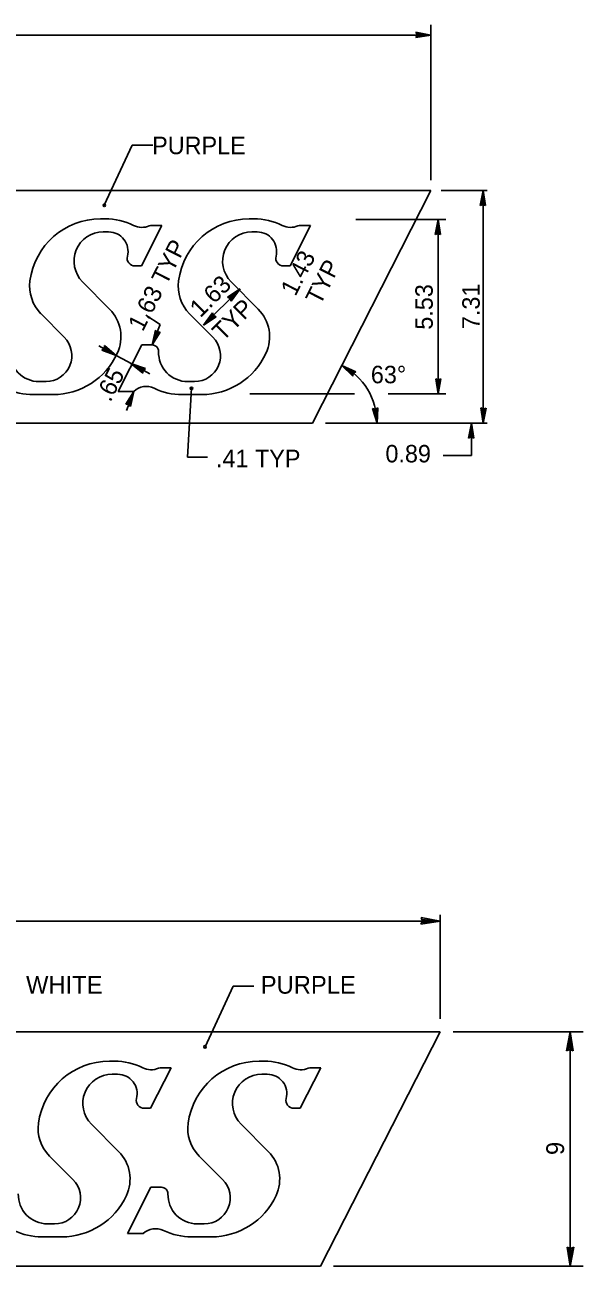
# Model space of a CAD drawing. Extents: x 10268197 to 10269179, y 2141503 to 2142677.
# Drawn here: x 10268622.88 to 10268641.86, y 2142123.35 to 2142165.55 of the extents above; entities that cross this region are included whole.
import ezdxf

# ---------------------------------------------------------------- set-up
doc = ezdxf.new("R2010")
doc.units = 0
for name, color, linetype in [('1', 7, 'Continuous'), ('21', 7, 'Continuous'), ('Default', 7, 'Continuous')]:
    doc.layers.add(name, color=color, linetype=linetype)

msp = doc.modelspace()

# ---------------------------------------------------------------- linework, layer by layer
at = {"layer": '1'}
for p, q in [((10268636.689, 2142160.267), (10268636.689, 2142165.546)), ((10268617.622, 2142165.194), (10268636.689, 2142165.194)), ((10268636.216, 2142165.203), (10268636.175, 2142165.112)), ((10268636.689, 2142165.194), (10268636.175, 2142165.112)), ((10268636.689, 2142165.194), (10268636.178, 2142165.293)), ((10268636.178, 2142165.293), (10268636.216, 2142165.203)), ((10268636.689, 2142165.194), (10268636.197, 2142165.16)), ((10268636.689, 2142165.194), (10268636.198, 2142165.246)), ((10268626.531, 2142161.456), (10268625.584, 2142159.412)), ((10268627.229, 2142161.456), (10268626.531, 2142161.456)), ((10268637.04, 2142159.916), (10268638.595, 2142159.916)), ((10268638.462, 2142159.916), (10268638.363, 2142159.405)), ((10268638.462, 2142159.916), (10268638.411, 2142159.424)), ((10268638.462, 2142152.007), (10268638.462, 2142159.916)), ((10268638.462, 2142159.916), (10268638.543, 2142159.402)), ((10268638.462, 2142159.916), (10268638.496, 2142159.424)), ((10268638.363, 2142159.405), (10268638.454, 2142159.442)), ((10268638.454, 2142159.442), (10268638.543, 2142159.402)), ((10268634.139, 2142158.927), (10268637.197, 2142158.927)), ((10268636.931, 2142158.927), (10268636.832, 2142158.416)), ((10268636.931, 2142158.927), (10268636.879, 2142158.436)), ((10268636.931, 2142152.996), (10268636.931, 2142158.927)), ((10268636.931, 2142158.927), (10268637.012, 2142158.413)), ((10268636.931, 2142158.927), (10268636.965, 2142158.435)), ((10268636.832, 2142158.416), (10268636.922, 2142158.454)), ((10268636.922, 2142158.454), (10268637.012, 2142158.413)), ((10268628.955, 2142155.33), (10268630.198, 2142156.573)), ((10268630.198, 2142156.573), (10268629.767, 2142156.282)), ((10268629.767, 2142156.282), (10268629.858, 2142156.244)), ((10268630.198, 2142156.573), (10268629.814, 2142156.262)), ((10268629.858, 2142156.244), (10268629.892, 2142156.152)), ((10268630.198, 2142156.573), (10268629.874, 2142156.201)), ((10268630.198, 2142156.573), (10268629.892, 2142156.152)), ((10268627.483, 2142155.362), (10268626.994, 2142155.673)), ((10268628.955, 2142155.33), (10268629.261, 2142155.751)), ((10268628.955, 2142155.33), (10268629.279, 2142155.702)), ((10268628.955, 2142155.33), (10268629.339, 2142155.641)), ((10268628.955, 2142155.33), (10268629.387, 2142155.622)), ((10268629.295, 2142155.659), (10268629.261, 2142155.751)), ((10268629.387, 2142155.622), (10268629.295, 2142155.659)), ((10268627.209, 2142154.662), (10268627.483, 2142155.362)), ((10268627.209, 2142154.662), (10268627.32, 2142155.171)), ((10268627.209, 2142154.662), (10268627.356, 2142155.133)), ((10268627.209, 2142154.662), (10268627.487, 2142155.102)), ((10268627.209, 2142154.662), (10268627.435, 2142155.101)), ((10268627.388, 2142155.1), (10268627.32, 2142155.171)), ((10268627.487, 2142155.102), (10268627.388, 2142155.1)), ((10268625.992, 2142154.306), (10268625.398, 2142154.63)), ((10268626.378, 2142154.096), (10268625.992, 2142154.306)), ((10268627.13, 2142153.686), (10268626.378, 2142154.096)), ((10268633.656, 2142153.965), (10268634.132, 2142153.753)), ((10268633.656, 2142153.965), (10268634.031, 2142153.603)), ((10268633.656, 2142153.965), (10268634.04, 2142153.654)), ((10268633.656, 2142153.965), (10268634.088, 2142153.726)), ((10268634.049, 2142153.7), (10268634.132, 2142153.753)), ((10268634.031, 2142153.603), (10268634.049, 2142153.7)), ((10268636.931, 2142152.996), (10268636.849, 2142153.51)), ((10268636.938, 2142153.469), (10268636.849, 2142153.51)), ((10268636.931, 2142152.996), (10268636.896, 2142153.488)), ((10268636.931, 2142152.996), (10268637.029, 2142153.507)), ((10268636.931, 2142152.996), (10268636.982, 2142153.487)), ((10268637.029, 2142153.507), (10268636.938, 2142153.469)), ((10268626.592, 2142153.085), (10268626.313, 2142152.645)), ((10268626.592, 2142153.085), (10268626.335, 2142152.43)), ((10268626.592, 2142153.085), (10268626.364, 2142152.646)), ((10268626.592, 2142153.085), (10268626.444, 2142152.614)), ((10268626.592, 2142153.085), (10268626.48, 2142152.576)), ((10268628.414, 2142150.852), (10268628.549, 2142153.189)), ((10268630.526, 2142152.996), (10268634.088, 2142152.996)), ((10268635.236, 2142152.996), (10268637.197, 2142152.996)), ((10268626.313, 2142152.645), (10268626.411, 2142152.647)), ((10268626.411, 2142152.647), (10268626.48, 2142152.576)), ((10268634.856, 2142152.007), (10268634.704, 2142152.505)), ((10268634.798, 2142152.477), (10268634.704, 2142152.505)), ((10268634.856, 2142152.007), (10268634.753, 2142152.49)), ((10268634.884, 2142152.527), (10268634.798, 2142152.477)), ((10268634.856, 2142152.007), (10268634.839, 2142152.501)), ((10268634.856, 2142152.007), (10268634.884, 2142152.527)), ((10268638.462, 2142152.007), (10268638.38, 2142152.521)), ((10268638.47, 2142152.48), (10268638.38, 2142152.521)), ((10268638.462, 2142152.007), (10268638.427, 2142152.499)), ((10268638.462, 2142152.007), (10268638.561, 2142152.518)), ((10268638.462, 2142152.007), (10268638.513, 2142152.499)), ((10268638.561, 2142152.518), (10268638.47, 2142152.48)), ((10268633.098, 2142152.007), (10268638.595, 2142152.007)), ((10268638.061, 2142152.007), (10268637.962, 2142151.497)), ((10268638.061, 2142152.007), (10268638.01, 2142151.516)), ((10268638.061, 2142150.909), (10268638.061, 2142152.007)), ((10268638.061, 2142152.007), (10268638.143, 2142151.494)), ((10268638.061, 2142152.007), (10268638.096, 2142151.515)), ((10268637.962, 2142151.497), (10268638.053, 2142151.534)), ((10268638.053, 2142151.534), (10268638.143, 2142151.494)), ((10268628.414, 2142150.852), (10268629.097, 2142150.852)), ((10268638.061, 2142150.909), (10268637.106, 2142150.909)), ((10268636.996, 2142131.752), (10268636.996, 2142135.291)), ((10268617.796, 2142135.07), (10268636.996, 2142135.07)), ((10268629.961, 2142132.861), (10268629.008, 2142130.802)), ((10268630.664, 2142132.861), (10268629.961, 2142132.861)), ((10268637.439, 2142131.31), (10268641.863, 2142131.31)), ((10268641.421, 2142123.346), (10268641.421, 2142131.31)), ((10268633.381, 2142123.346), (10268641.863, 2142123.346))]:
    msp.add_line(p, q, dxfattribs=at)
for centre, radius in [((10268625.584, 2142159.412), 0.0439), ((10268628.549, 2142153.189), 0.0439), ((10268629.008, 2142130.802), 0.0442)]:
    msp.add_circle(centre, radius, dxfattribs=at)
msp.add_arc((10268632.659, 2142152.008), 2.197, 0, 63.0012, dxfattribs=at)
at = {"layer": '21'}
for p, q in [((10268625.59, 2142154.639), (10268625.58, 2142154.54)), ((10268625.992, 2142154.306), (10268625.585, 2142154.587)), ((10268625.992, 2142154.306), (10268625.59, 2142154.639)), ((10268625.58, 2142154.54), (10268625.501, 2142154.481)), ((10268625.992, 2142154.306), (10268625.501, 2142154.481)), ((10268625.992, 2142154.306), (10268625.543, 2142154.512)), ((10268626.49, 2142154.032), (10268626.981, 2142153.858)), ((10268626.49, 2142154.032), (10268626.892, 2142153.7)), ((10268626.49, 2142154.032), (10268626.897, 2142153.752)), ((10268626.49, 2142154.032), (10268626.939, 2142153.826)), ((10268626.892, 2142153.7), (10268626.902, 2142153.798)), ((10268626.902, 2142153.798), (10268626.981, 2142153.858))]:
    msp.add_line(p, q, dxfattribs=at)
at = {"layer": 'Default'}
for p, q in [((10268611.626, 2142159.916), (10268636.689, 2142159.916)), ((10268632.66, 2142152.007), (10268636.689, 2142159.916)), ((10268625.453, 2142158.949), (10268625.619, 2142158.949)), ((10268630.505, 2142158.949), (10268630.672, 2142158.949)), ((10268625.731, 2142158.507), (10268625.542, 2142158.507)), ((10268627.543, 2142158.728), (10268626.845, 2142157.347)), ((10268627.213, 2142158.728), (10268627.543, 2142158.728)), ((10268630.783, 2142158.507), (10268630.594, 2142158.507)), ((10268632.595, 2142158.728), (10268631.897, 2142157.347)), ((10268632.266, 2142158.728), (10268632.595, 2142158.728)), ((10268626.845, 2142157.347), (10268626.625, 2142157.347)), ((10268631.897, 2142157.347), (10268631.677, 2142157.347)), ((10268624.843, 2142156.806), (10268625.764, 2142155.879)), ((10268629.896, 2142156.806), (10268630.817, 2142155.879)), ((10268624.223, 2142154.928), (10268623.432, 2142155.724)), ((10268629.275, 2142154.928), (10268628.484, 2142155.724)), ((10268626.058, 2142153.085), (10268626.856, 2142154.662)), ((10268626.856, 2142154.662), (10268627.209, 2142154.662)), ((10268623.364, 2142153.417), (10268623.602, 2142153.417)), ((10268628.417, 2142153.417), (10268628.654, 2142153.417)), ((10268623.837, 2142152.974), (10268623.177, 2142152.974)), ((10268626.592, 2142153.085), (10268626.058, 2142153.085)), ((10268628.89, 2142152.974), (10268628.229, 2142152.974)), ((10268610.892, 2142152.007), (10268632.66, 2142152.007)), ((10268636.996, 2142135.07), (10268636.353, 2142135.195)), ((10268636.353, 2142135.195), (10268636.401, 2142135.08)), ((10268636.401, 2142135.08), (10268636.349, 2142134.967)), ((10268636.996, 2142135.07), (10268636.349, 2142134.967)), ((10268636.996, 2142135.07), (10268636.377, 2142135.027)), ((10268636.996, 2142135.07), (10268636.378, 2142135.135)), ((10268611.758, 2142131.31), (10268636.996, 2142131.31)), ((10268632.938, 2142123.346), (10268636.996, 2142131.31)), ((10268641.421, 2142131.31), (10268641.296, 2142130.667)), ((10268641.421, 2142131.31), (10268641.356, 2142130.692)), ((10268641.421, 2142131.31), (10268641.523, 2142130.663)), ((10268641.421, 2142131.31), (10268641.464, 2142130.69)), ((10268641.296, 2142130.667), (10268641.41, 2142130.714)), ((10268641.41, 2142130.714), (10268641.523, 2142130.663)), ((10268625.757, 2142130.314), (10268625.925, 2142130.314)), ((10268627.862, 2142130.092), (10268627.158, 2142128.713)), ((10268627.53, 2142130.092), (10268627.862, 2142130.092)), ((10268630.845, 2142130.314), (10268631.013, 2142130.314)), ((10268632.95, 2142130.092), (10268632.247, 2142128.713)), ((10268632.618, 2142130.092), (10268632.95, 2142130.092)), ((10268626.037, 2142129.871), (10268625.848, 2142129.871)), ((10268631.125, 2142129.871), (10268630.935, 2142129.871)), ((10268627.158, 2142128.713), (10268626.937, 2142128.713)), ((10268632.247, 2142128.713), (10268632.025, 2142128.713)), ((10268625.143, 2142128.172), (10268626.071, 2142127.245)), ((10268630.232, 2142128.172), (10268631.159, 2142127.245)), ((10268624.518, 2142126.294), (10268623.722, 2142127.09)), ((10268629.606, 2142126.294), (10268628.811, 2142127.09)), ((10268626.367, 2142124.452), (10268627.17, 2142126.029)), ((10268627.17, 2142126.029), (10268627.526, 2142126.029)), ((10268623.654, 2142124.783), (10268623.893, 2142124.783)), ((10268628.742, 2142124.783), (10268628.98, 2142124.783)), ((10268624.131, 2142124.341), (10268623.465, 2142124.341)), ((10268626.904, 2142124.452), (10268626.367, 2142124.452)), ((10268629.218, 2142124.341), (10268628.553, 2142124.341)), ((10268641.421, 2142123.346), (10268641.318, 2142123.993)), ((10268641.43, 2142123.941), (10268641.318, 2142123.993)), ((10268641.421, 2142123.346), (10268641.377, 2142123.965)), ((10268641.421, 2142123.346), (10268641.545, 2142123.989)), ((10268641.421, 2142123.346), (10268641.485, 2142123.964)), ((10268641.545, 2142123.989), (10268641.43, 2142123.941)), ((10268611.171, 2142123.346), (10268632.938, 2142123.346))]:
    msp.add_line(p, q, dxfattribs=at)
for centre, radius, start, end in [((10268625.757, 2142127.88), 2.433, 90, 172.3089), ((10268625.925, 2142128.101), 2.212, 64.0896, 90), ((10268627.181, 2142130.688), 0.664, 244.0896, 292.0347), ((10268627.53, 2142129.827), 0.265, 90, 112.0347), ((10268630.845, 2142127.88), 2.433, 90, 172.3089), ((10268631.013, 2142128.101), 2.212, 64.0896, 90), ((10268632.269, 2142130.688), 0.664, 244.0896, 292.0347), ((10268632.618, 2142129.827), 0.265, 90, 112.0347), ((10268625.847, 2142128.876), 0.995, 90, 225), ((10268626.037, 2142129.207), 0.664, 345.6915, 90), ((10268630.935, 2142128.876), 0.995, 90, 225), ((10268631.125, 2142129.207), 0.664, 345.6915, 90), ((10268626.937, 2142128.978), 0.265, 165.6915, 270), ((10268632.025, 2142128.978), 0.265, 165.6915, 270), ((10268624.661, 2142128.028), 1.327, 172.3089, 225), ((10268629.749, 2142128.028), 1.327, 172.3089, 225), ((10268625.132, 2142126.306), 1.327, 334.95, 45), ((10268630.22, 2142126.306), 1.327, 334.95, 45), ((10268623.892, 2142125.668), 0.885, 270, 45), ((10268628.98, 2142125.668), 0.885, 270, 45), ((10268627.526, 2142125.807), 0.221, 358.6664, 90), ((10268623.654, 2142125.779), 0.995, 178.6665, 270), ((10268624.13, 2142126.774), 2.433, 270, 334.95), ((10268628.742, 2142125.779), 0.995, 178.6665, 270), ((10268629.218, 2142126.774), 2.433, 270, 334.95), ((10268627.328, 2142124), 0.619, 64.3795, 133.1892), ((10268623.465, 2142126.553), 2.212, 244.3795, 270), ((10268628.553, 2142126.553), 2.212, 244.3795, 270)]:
    msp.add_arc(centre, radius, start, end, dxfattribs=at)
for centre, major_axis, start_param, end_param in [((10268625.452, 2142156.515), (0, 2.434), 0, 1.436562), ((10268625.619, 2142156.736), (0, 2.213), 5.830963, 6.283185), ((10268630.505, 2142156.515), (0, 2.434), 0, 1.436562), ((10268630.672, 2142156.736), (0, 2.213), 5.830963, 6.283185), ((10268625.542, 2142157.511), (0, -0.996), 3.141593, 5.497787), ((10268625.731, 2142157.843), (0, -0.664), 1.321066, 3.141593), ((10268626.867, 2142159.324), (0, 0.664), 2.68937, 3.526171), ((10268627.213, 2142158.463), (0, 0.266), 0, 0.384579), ((10268630.595, 2142157.511), (0, -0.996), 3.141593, 5.497787), ((10268630.783, 2142157.843), (0, -0.664), 1.321066, 3.141593), ((10268631.919, 2142159.324), (0, 0.664), 2.68937, 3.526171), ((10268632.266, 2142158.463), (0, 0.266), 0, 0.384579), ((10268626.625, 2142157.613), (0, -0.266), 4.462658, 6.283185), ((10268631.677, 2142157.613), (0, -0.266), 4.462658, 6.283185), ((10268624.364, 2142156.663), (0, 1.328), 1.436562, 2.356194), ((10268629.416, 2142156.663), (0, 1.328), 1.436562, 2.356194), ((10268624.832, 2142154.94), (0, -1.328), 1.133591, 2.356194), ((10268629.885, 2142154.94), (0, -1.328), 1.133591, 2.356194), ((10268623.601, 2142154.302), (0, -0.885), 0, 2.356194), ((10268627.209, 2142154.441), (0, 0.221), 4.689114, 6.283185), ((10268628.654, 2142154.302), (0, -0.885), 0, 2.356194), ((10268623.364, 2142154.413), (0, 0.996), 1.547521, 3.141593), ((10268623.837, 2142155.408), (0, -2.434), 0, 1.133591), ((10268628.417, 2142154.413), (0, 0.996), 1.547521, 3.141593), ((10268628.89, 2142155.408), (0, -2.434), 0, 1.133591), ((10268627.013, 2142152.633), (0, -0.62), 2.69443, 3.895387), ((10268623.176, 2142155.187), (0, -2.213), 5.836023, 6.283185), ((10268628.229, 2142155.187), (0, -2.213), 5.836023, 6.283185)]:
    msp.add_ellipse(centre, major_axis=major_axis, ratio=0.992614, start_param=start_param, end_param=end_param, dxfattribs=at)

# ---------------------------------------------------------------- texts
at = {"layer": '1'}
for s, height, p in [('PURPLE', 0.5942, (10268627.211, 2142161.148)), ('63°', 0.5942, (10268634.646, 2142153.36)), ('0.89', 0.5942, (10268635.141, 2142150.67)), ('.41 TYP', 0.5942, (10268629.381, 2142150.507)), ('WHITE', 0.6037, (10268622.923, 2142132.609)), ('PURPLE', 0.6037, (10268630.903, 2142132.609))]:
    msp.add_text(s, height=height, dxfattribs=at).set_placement(p)
for s, height, rotation, p in [('1.63 TYP', 0.5942, 62.9994, (10268626.89, 2142155.09)), ('1.43', 0.5942, 63, (10268632.08, 2142156.29)), ('TYP', 0.5942, 63, (10268632.925, 2142155.985)), ('1.63', 0.5942, 45, (10268628.851, 2142155.57)), ('5.53', 0.5942, 90, (10268636.75, 2142155.182)), ('7.31', 0.5942, 90, (10268638.346, 2142155.202)), ('TYP', 0.5942, 45, (10268629.613, 2142154.768)), ('.65', 0.5942, 63, (10268625.788, 2142152.695)), ('9', 0.604, 90, (10268641.213, 2142127.123))]:
    msp.add_text(s, height=height, rotation=rotation, dxfattribs=at).set_placement(p)

doc.saveas('drawing.dxf')
